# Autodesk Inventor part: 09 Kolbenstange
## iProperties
Created: 2010-07
Part Number: 09 Kolbenstange
Material: 1.4301 X5CrNi10-10 A2
Document SubType Name: Modeling
Designer: F. Lattrell
Mass: 1840.56 g
Surface Area: 370.554 cm^2
Volume: 234.167 cm^3
Density: 7.86 g/cm^3
Author: F. Lattrell
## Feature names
1. Umdrehung1 [Revolution]
2. Bohrung1 [Hole]
3. Bohrung2 [Hole]
4. Fase1 [Chamfer]
5. Umdrehung2 [Revolution]
6. Fase2 [Chamfer]
7. Extrusion1
8. Bohrung3 [Hole]
